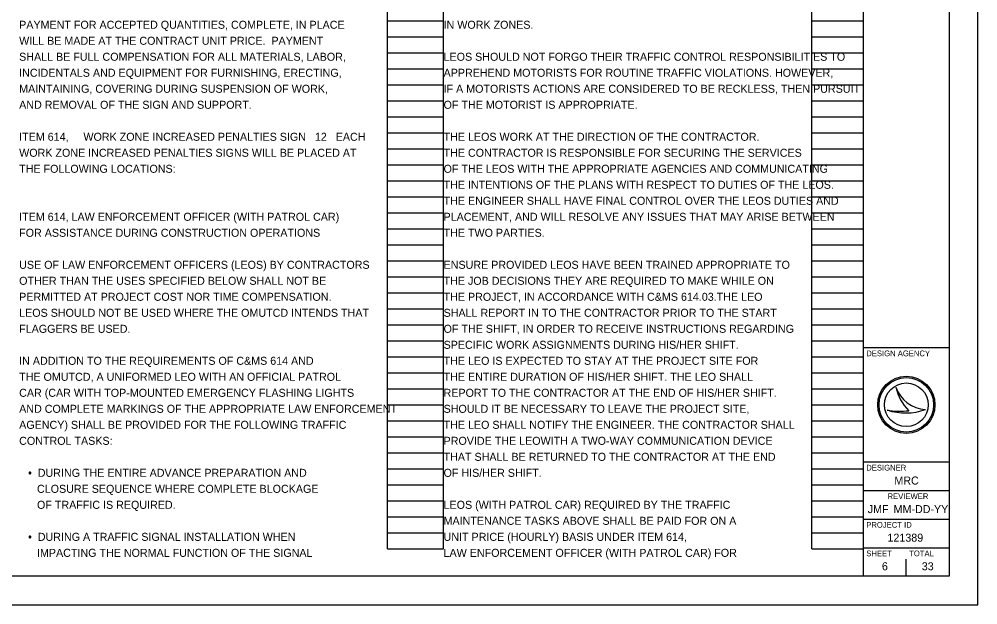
# Model space of a CAD drawing. Extents: x 0 to 34, y 0 to 22.
# Drawn here: x 17.24 to 34, y 0 to 10.25 of the extents above; entities that cross this region are included whole.
import ezdxf

# ---------------------------------------------------------------- set-up
doc = ezdxf.new("R2010")
doc.units = 0
for name, color, linetype in [('SH_Border', 7, 'Continuous'), ('SH_Cut_Line', 7, 'Continuous'), ('SH_Data', 7, 'Continuous'), ('SH_Text', 7, 'Continuous')]:
    doc.layers.add(name, color=color, linetype=linetype)

msp = doc.modelspace()

# ---------------------------------------------------------------- linework, layer by layer
at = {"layer": 'SH_Border'}
for p, q in [((32, 0.5), (32, 21.5)), ((32, 4.5), (33.5, 4.5)), ((32, 2.5), (33.5, 2.5)), ((32, 2), (33.5, 2)), ((32, 1.5), (33.5, 1.5)), ((32, 1), (33.5, 1))]:
    msp.add_line(p, q, dxfattribs=at)
msp.add_lwpolyline([(1.5, 21.5), (33.5, 21.5), (33.5, 0.5), (1.5, 0.5)], close=True, dxfattribs=at)
at = {"layer": 'SH_Cut_Line'}
msp.add_lwpolyline([(0, 0), (34, 0), (34, 22), (0, 22)], close=True, dxfattribs=at)
at = {"layer": 'SH_Data'}
for p, q in [((23.68, 0.98), (23.68, 21.14)), ((24.66, 0.98), (24.66, 21.14)), ((31.1, 0.98), (31.1, 21.14)), ((32, 0.98), (32, 21.14)), ((23.68, 10.22), (24.66, 10.22)), ((31.1, 10.22), (32, 10.22)), ((23.68, 9.94), (24.66, 9.94)), ((31.1, 9.94), (32, 9.94)), ((23.68, 9.66), (24.66, 9.66)), ((31.1, 9.66), (32, 9.66)), ((23.68, 9.38), (24.66, 9.38)), ((31.1, 9.38), (32, 9.38)), ((23.68, 9.1), (24.66, 9.1)), ((31.1, 9.1), (32, 9.1)), ((23.68, 8.82), (24.66, 8.82)), ((31.1, 8.82), (32, 8.82)), ((23.68, 8.54), (24.66, 8.54)), ((31.1, 8.54), (32, 8.54)), ((23.68, 8.26), (24.66, 8.26)), ((31.1, 8.26), (32, 8.26)), ((23.68, 7.98), (24.66, 7.98)), ((31.1, 7.98), (32, 7.98)), ((23.68, 7.7), (24.66, 7.7)), ((31.1, 7.7), (32, 7.7)), ((23.68, 7.42), (24.66, 7.42)), ((31.1, 7.42), (32, 7.42)), ((23.68, 7.14), (24.66, 7.14)), ((31.1, 7.14), (32, 7.14)), ((23.68, 6.86), (24.66, 6.86)), ((31.1, 6.86), (32, 6.86)), ((23.68, 6.58), (24.66, 6.58)), ((31.1, 6.58), (32, 6.58)), ((23.68, 6.3), (24.66, 6.3)), ((31.1, 6.3), (32, 6.3)), ((23.68, 6.02), (24.66, 6.02)), ((31.1, 6.02), (32, 6.02)), ((23.68, 5.74), (24.66, 5.74)), ((31.1, 5.74), (32, 5.74)), ((23.68, 5.46), (24.66, 5.46)), ((31.1, 5.46), (32, 5.46)), ((23.68, 5.18), (24.66, 5.18)), ((31.1, 5.18), (32, 5.18)), ((23.68, 4.9), (24.66, 4.9)), ((31.1, 4.9), (32, 4.9)), ((23.68, 4.62), (24.66, 4.62)), ((31.1, 4.62), (32, 4.62)), ((23.68, 4.34), (24.66, 4.34)), ((31.1, 4.34), (32, 4.34)), ((23.68, 4.06), (24.66, 4.06)), ((31.1, 4.06), (32, 4.06)), ((23.68, 3.78), (24.66, 3.78)), ((31.1, 3.78), (32, 3.78)), ((32.567, 3.81), (32.567, 3.81)), ((23.68, 3.5), (24.66, 3.5)), ((31.1, 3.5), (32, 3.5)), ((32.417, 3.41), (32.417, 3.41)), ((32.75, 3.5), (32.75, 3.5)), ((33.087, 3.419), (33.087, 3.419)), ((23.68, 3.22), (24.66, 3.22)), ((31.1, 3.22), (32, 3.22)), ((23.68, 2.94), (24.66, 2.94)), ((31.1, 2.94), (32, 2.94)), ((23.68, 2.66), (24.66, 2.66)), ((31.1, 2.66), (32, 2.66)), ((23.68, 2.38), (24.66, 2.38)), ((31.1, 2.38), (32, 2.38)), ((23.68, 2.1), (24.66, 2.1)), ((31.1, 2.1), (32, 2.1)), ((23.68, 1.82), (24.66, 1.82)), ((31.1, 1.82), (32, 1.82)), ((23.68, 1.54), (24.66, 1.54)), ((31.1, 1.54), (32, 1.54)), ((23.68, 1.26), (24.66, 1.26)), ((31.1, 1.26), (32, 1.26)), ((23.68, 0.98), (24.66, 0.98)), ((31.1, 0.98), (32, 0.98)), ((32.375, 0.675), (32.375, 0.675)), ((32.75, 0.5), (32.75, 0.8))]:
    msp.add_line(p, q, dxfattribs=at)
for radius in [0.5, 0.477, 0.477, 0.382]:
    msp.add_circle((32.75, 3.5), radius, dxfattribs=at)
for centre, radius, start, end in [((33.116, 3.998), 0.58, 198.9257, 198.9319), ((33.347, 3.97), 0.796, 191.6379, 191.6421), ((33.116, 3.998), 0.58, 198.9319, 267.1657), ((33.347, 3.97), 0.796, 191.6421, 226.0947), ((32.739, 4.37), 1.013, 251.4576, 290.0832), ((32.648, 4.654), 1.266, 259.4964, 259.4995), ((32.739, 4.37), 1.013, 251.4527, 251.4576), ((32.648, 4.654), 1.266, 259.4995, 276.6672)]:
    msp.add_arc(centre, radius, start, end, dxfattribs=at)

# ---------------------------------------------------------------- texts
for s, height, p in [('DESIGN AGENCY', 0.1, (32.05, 4.35)), ('DESIGNER', 0.1, (32.05, 2.35)), ('MRC', 0.14, (32.541, 2.105)), ('REVIEWER', 0.1, (32.422, 1.85)), ('JMF', 0.14, (32.075, 1.605)), ('MM-DD-YY', 0.14, (32.527, 1.605)), ('PROJECT ID', 0.1, (32.05, 1.35)), ('121389', 0.14, (32.42, 1.105)), ('SHEET', 0.1, (32.05, 0.85)), ('TOTAL', 0.1, (32.8, 0.85)), ('6', 0.14, (32.323, 0.605)), ('33', 0.14, (33.02, 0.605))]:
    msp.add_text(s, height=height, dxfattribs=at).set_placement(p)
at = {"layer": 'SH_Text'}
for s, p in [('PAYMENT FOR ACCEPTED QUANTITIES, COMPLETE, IN PLACE', (17.24, 10.08)), ('IN WORK ZONES.', (24.66, 10.08)), ('WILL BE MADE AT THE CONTRACT UNIT PRICE.  PAYMENT', (17.24, 9.8)), ('SHALL BE FULL COMPENSATION FOR ALL MATERIALS, LABOR,', (17.24, 9.52)), ('LEOS SHOULD NOT FORGO THEIR TRAFFIC CONTROL RESPONSIBILITIES TO', (24.66, 9.52)), ('INCIDENTALS AND EQUIPMENT FOR FURNISHING, ERECTING,', (17.24, 9.24)), ('APPREHEND MOTORISTS FOR ROUTINE TRAFFIC VIOLATIONS. HOWEVER,', (24.66, 9.24)), ('MAINTAINING, COVERING DURING SUSPENSION OF WORK,', (17.24, 8.96)), ('IF A MOTORISTS ACTIONS ARE CONSIDERED TO BE RECKLESS, THEN PURSUIT', (24.66, 8.96)), ('AND REMOVAL OF THE SIGN AND SUPPORT.', (17.24, 8.68)), ('OF THE MOTORIST IS APPROPRIATE.', (24.66, 8.68)), ('ITEM 614,     WORK ZONE INCREASED PENALTIES SIGN   12   EACH', (17.24, 8.12)), ('THE LEOS WORK AT THE DIRECTION OF THE CONTRACTOR.', (24.66, 8.12)), ('WORK ZONE INCREASED PENALTIES SIGNS WILL BE PLACED AT', (17.24, 7.84)), ('THE CONTRACTOR IS RESPONSIBLE FOR SECURING THE SERVICES', (24.66, 7.84)), ('THE FOLLOWING LOCATIONS:', (17.24, 7.56)), ('OF THE LEOS WITH THE APPROPRIATE AGENCIES AND COMMUNICATING', (24.66, 7.56)), ('THE INTENTIONS OF THE PLANS WITH RESPECT TO DUTIES OF THE LEOS.', (24.66, 7.28)), ('THE ENGINEER SHALL HAVE FINAL CONTROL OVER THE LEOS DUTIES AND', (24.66, 7)), ('ITEM 614, LAW ENFORCEMENT OFFICER (WITH PATROL CAR)', (17.24, 6.72)), ('PLACEMENT, AND WILL RESOLVE ANY ISSUES THAT MAY ARISE BETWEEN', (24.66, 6.72)), ('FOR ASSISTANCE DURING CONSTRUCTION OPERATIONS', (17.24, 6.44)), ('THE TWO PARTIES.', (24.66, 6.44)), ('USE OF LAW ENFORCEMENT OFFICERS (LEOS) BY CONTRACTORS', (17.24, 5.88)), ('ENSURE PROVIDED LEOS HAVE BEEN TRAINED APPROPRIATE TO', (24.66, 5.88)), ('OTHER THAN THE USES SPECIFIED BELOW SHALL NOT BE', (17.24, 5.6)), ('THE JOB DECISIONS THEY ARE REQUIRED TO MAKE WHILE ON', (24.66, 5.6)), ('PERMITTED AT PROJECT COST NOR TIME COMPENSATION.', (17.24, 5.32)), ('THE PROJECT, IN ACCORDANCE WITH C&MS 614.03.THE LEO', (24.66, 5.32)), ('LEOS SHOULD NOT BE USED WHERE THE OMUTCD INTENDS THAT', (17.24, 5.04)), ('SHALL REPORT IN TO THE CONTRACTOR PRIOR TO THE START', (24.66, 5.04)), ('FLAGGERS BE USED.', (17.24, 4.76)), ('OF THE SHIFT, IN ORDER TO RECEIVE INSTRUCTIONS REGARDING', (24.66, 4.76)), ('SPECIFIC WORK ASSIGNMENTS DURING HIS/HER SHIFT.', (24.66, 4.48)), ('IN ADDITION TO THE REQUIREMENTS OF C&MS 614 AND', (17.24, 4.2)), ('THE LEO IS EXPECTED TO STAY AT THE PROJECT SITE FOR', (24.66, 4.2)), ('THE OMUTCD, A UNIFORMED LEO WITH AN OFFICIAL PATROL', (17.24, 3.92)), ('THE ENTIRE DURATION OF HIS/HER SHIFT. THE LEO SHALL', (24.66, 3.92)), ('CAR (CAR WITH TOP-MOUNTED EMERGENCY FLASHING LIGHTS', (17.24, 3.64)), ('REPORT TO THE CONTRACTOR AT THE END OF HIS/HER SHIFT.', (24.66, 3.64)), ('AND COMPLETE MARKINGS OF THE APPROPRIATE LAW ENFORCEMENT', (17.24, 3.36)), ('SHOULD IT BE NECESSARY TO LEAVE THE PROJECT SITE,', (24.66, 3.36)), ('AGENCY) SHALL BE PROVIDED FOR THE FOLLOWING TRAFFIC', (17.24, 3.08)), ('THE LEO SHALL NOTIFY THE ENGINEER. THE CONTRACTOR SHALL', (24.66, 3.08)), ('CONTROL TASKS:', (17.24, 2.8)), ('PROVIDE THE LEOWITH A TWO-WAY COMMUNICATION DEVICE', (24.66, 2.8)), ('THAT SHALL BE RETURNED TO THE CONTRACTOR AT THE END', (24.66, 2.52)), ('   •  DURING THE ENTIRE ADVANCE PREPARATION AND', (17.24, 2.24)), ('OF HIS/HER SHIFT.', (24.66, 2.24)), ('      CLOSURE SEQUENCE WHERE COMPLETE BLOCKAGE', (17.24, 1.96)), ('      OF TRAFFIC IS REQUIRED.', (17.24, 1.68)), ('LEOS (WITH PATROL CAR) REQUIRED BY THE TRAFFIC', (24.66, 1.68)), ('MAINTENANCE TASKS ABOVE SHALL BE PAID FOR ON A', (24.66, 1.4)), ('   •  DURING A TRAFFIC SIGNAL INSTALLATION WHEN', (17.24, 1.12)), ('UNIT PRICE (HOURLY) BASIS UNDER ITEM 614,', (24.66, 1.12)), ('      IMPACTING THE NORMAL FUNCTION OF THE SIGNAL', (17.24, 0.84)), ('LAW ENFORCEMENT OFFICER (WITH PATROL CAR) FOR', (24.66, 0.84))]:
    msp.add_text(s, height=0.14, dxfattribs=at).set_placement(p)

doc.saveas('drawing.dxf')
